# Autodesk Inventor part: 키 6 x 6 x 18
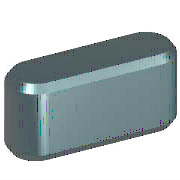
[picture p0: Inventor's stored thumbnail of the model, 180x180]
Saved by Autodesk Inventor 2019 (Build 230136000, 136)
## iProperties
IsCustomPart: 1
Created: 2012-02
Part Number: 키 6 x 6 x 18
Material: 강철, 연강
Description: 키 및 해당 키홈
Document SubType Name: Modeling
Standard: KS B 1311
Designer: mduedu
Standards Organization: KS
Language: ko-KR
Size Designation: 6 x 6 x 18
Categories: <MemberInstance><Categories><Category DisplayName="샤프트 부품" InternalName="7f7aeb1f-a693-4053-b835-cee3144e0d98" Mnemonic="SHFT"><Category DisplayName="키" Interna
Density: 1 g/cm^3
Appearance: 노란색
Author: mduedu
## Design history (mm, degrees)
workplane "Work Plane1"
workplane "Work Plane2"
sketch "스케치1"
  geometry: L1 (3, 3)-(15, 3); L2 (15, -3)-(3, -3); L3 (0, 9.4)-(0, -7.4) reference; L4 (-5, 0)-(30, 0) reference; L5 (18, 0)-(18, 7); A1 r 3 centre (3, 0) between (3, 3) and (3, -3); A2 r 3 centre (15, 0) between (15, -3) and (15, 3)
  constraints: 6 end point, 5 point on circle, 4 tangent, 3 point on line, 2 centre point, 1 horizontal, 1 parallel, 1 perpendicular
  dimensions: "d0" = 3 radius of A1 (= 0.5 x PB); "d13" = 3 radius of A2 (= 0.5 x PB); "d14" = 18 distance between parallel lines of L5 L3 (= NLG)
extrude "본체1" new body sketch "스케치1" taper "d3" = 0 deg; stored distance "d4" = 10
workplane "Work Plane3"
body "Solid1"
chamfer "모따기1" distance "d8" = 0.4 (= PHH); stored, may be unused: second distance "d9" = 0.4 (= PHH), angle "d15" = 45 deg
other parameters: "d1" = -3.5 (= -PNT), "d2" = 2.5 (= PH - PNT), "NLG" = 18 [user parameter; used in 3 equation terms], "PB" = 6 [user parameter; used in 2 equation terms], "PNT" = 3.5 [user parameter; used in 2 equation terms], "PH" = 6 [user parameter; used in 1 equation term], "PHH" = 0.4 [user parameter; used in 2 equation terms], "d10" = 0, "d16" = 0, "d17" = 0, "d18" = 0, "WDMIN" = 17 [user parameter], "PLB2" = 18 (= NLG) [user parameter], "WDMAX" = 22 [user parameter], "PLB1" = 18 (= NLG) [user parameter], "RR" = 0.16 [user parameter], "PUEB" = 2.8 [user parameter]
